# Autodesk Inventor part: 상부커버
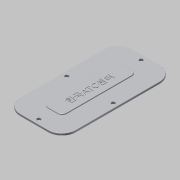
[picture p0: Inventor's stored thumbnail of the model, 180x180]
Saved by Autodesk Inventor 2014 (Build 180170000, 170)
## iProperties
Created: 2016-02
Part Number: 상부커버
Material: 알루미늄 6061
Document SubType Name: Modeling
Designer: mduedu
Density: 2.71 g/cm^3
Mass: 42.0587 g
Surface Area: 149.263 cm^2
Volume: 15.5198 cm^3
Appearance: 알루미늄 - 평지
Author: mduedu
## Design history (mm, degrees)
sketch "스케치1"
  geometry: L1 (30, 60)-(-30, 60); L2 (-30, 60)-(-30, -60); L3 (-30, -60)-(30, -60); L4 (30, -60)-(30, 60); L5 (30, 60)-(-30, -60); L6 (-30, 60)-(30, -60); 1 further point
  constraints: 12 end point, 2 midpoint, 2 parallel, 1 horizontal, 1 perpendicular
  dimensions: "d0" = 60 distance of L2.end L3.end; "d2" = 120 distance of L1.end L2.end
extrude "돌출1" new body sketch "스케치1" distance "d3" = 2; taper "d4" = 0 deg
fillet "모깎기1" dims "d5" = 15
sketch "스케치2"
  geometry: L1 (30, 45)-(30, -45) reference; L2 (15, -60)-(-15, -60) reference; L3 (-30, -45)-(-30, 45) reference; L4 (-15, 60)-(15, 60) reference; L5 (25, 45)-(25, -45); L6 (15, -55)-(-15, -55); L7 (-25, -45)-(-25, 45); L8 (-15, 55)-(15, 55); A1 r 15 centre (15, 45) between (30, 45) and (15, 60) reference; A2 r 15 centre (15, -45) between (15, -60) and (30, -45) reference; A3 r 15 centre (-15, -45) between (-30, -45) and (-15, -60) reference; A4 r 15 centre (-15, 45) between (-15, 60) and (-30, 45) reference; A5 r 10 centre (15, 45) between (25, 45) and (15, 55); A6 r 10 centre (15, -45) between (15, -55) and (25, -45); A7 r 10 centre (-15, -45) between (-25, -45) and (-15, -55); A8 r 10 centre (-15, 45) between (-15, 55) and (-25, 45); 4 further points
  constraints: 8 end point, 8 point on circle, 4 centre point, 4 midpoint, 7 other
  dimensions: "d8" = 5 distance between parallel lines of L7 L3
hole "구멍1" sketch "스케치2" at (0, 55), (25, 0), (0, -55), (-25, 0) diameter "d9" = 4; stored, may be unused: countersink angle "d13" = 90 deg, drill point angle "d15" = 118 deg; dims "d10" = 6, "d11" = 4, "d12" = 2, "d14" = 8
sketch "스케치3"
  geometry: L1 (10, -40)-(-10, -40); L2 (-10, -40)-(-10, 40); L3 (-10, 40)-(10, 40); L4 (10, 40)-(10, -40); L5 (10, -40)-(-10, 40); L6 (-10, -40)-(10, 40); 1 further point
  constraints: 12 end point, 2 midpoint, 2 parallel, 1 horizontal, 1 perpendicular
  dimensions: "d16" = 80 distance of L1.end L2.end; "d18" = 20 distance of L2.end L3.end
extrude "돌출2" join sketch "스케치3" distance "d19" = 1; taper "d20" = 0 deg
fillet "모깎기2" dims "d21" = 5
fillet "모깎기3" dims "d22" = 0.3
fillet "모깎기4" dims "d23" = 0.3
sketch "스케치4"
  geometry: 2 further points
  constraints: 1 coincident, 1 other
feature "엠보싱1" sketch "스케치4" dims "d0" = 60, "d2" = 120, "d8" = 5, "d24" = 0.5, "d25" = 0
node "솔리드1"
node "절단 모서리 투영1"
